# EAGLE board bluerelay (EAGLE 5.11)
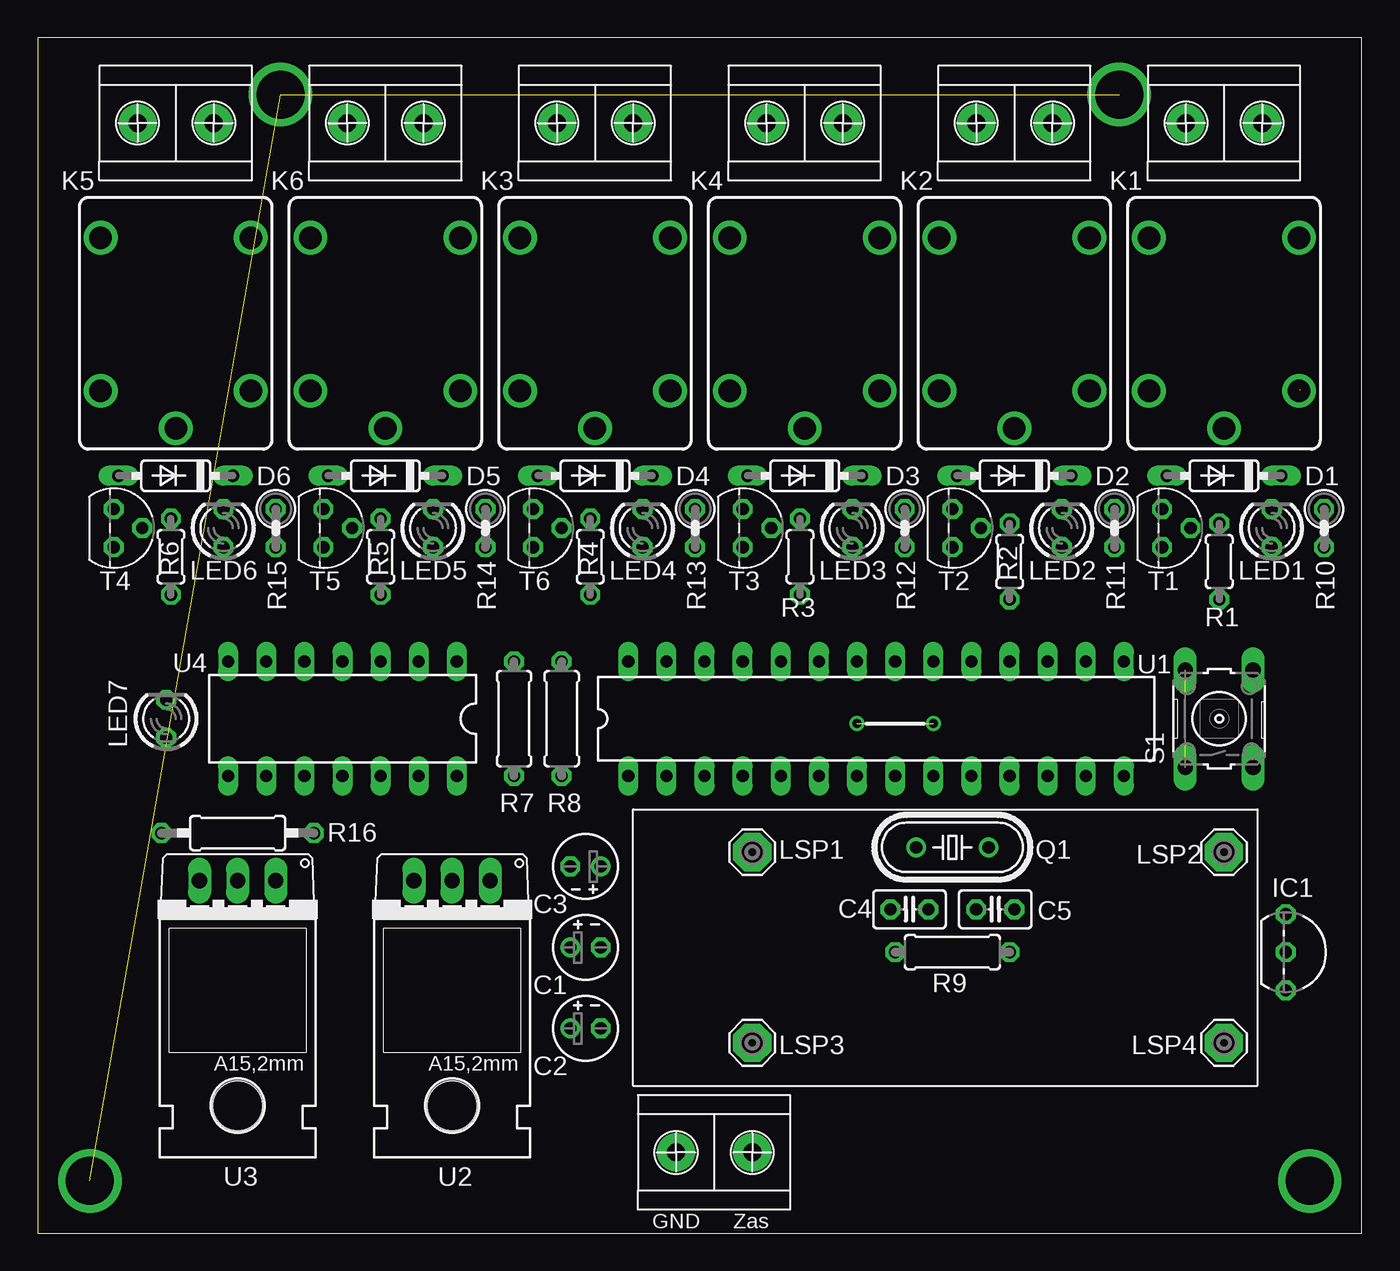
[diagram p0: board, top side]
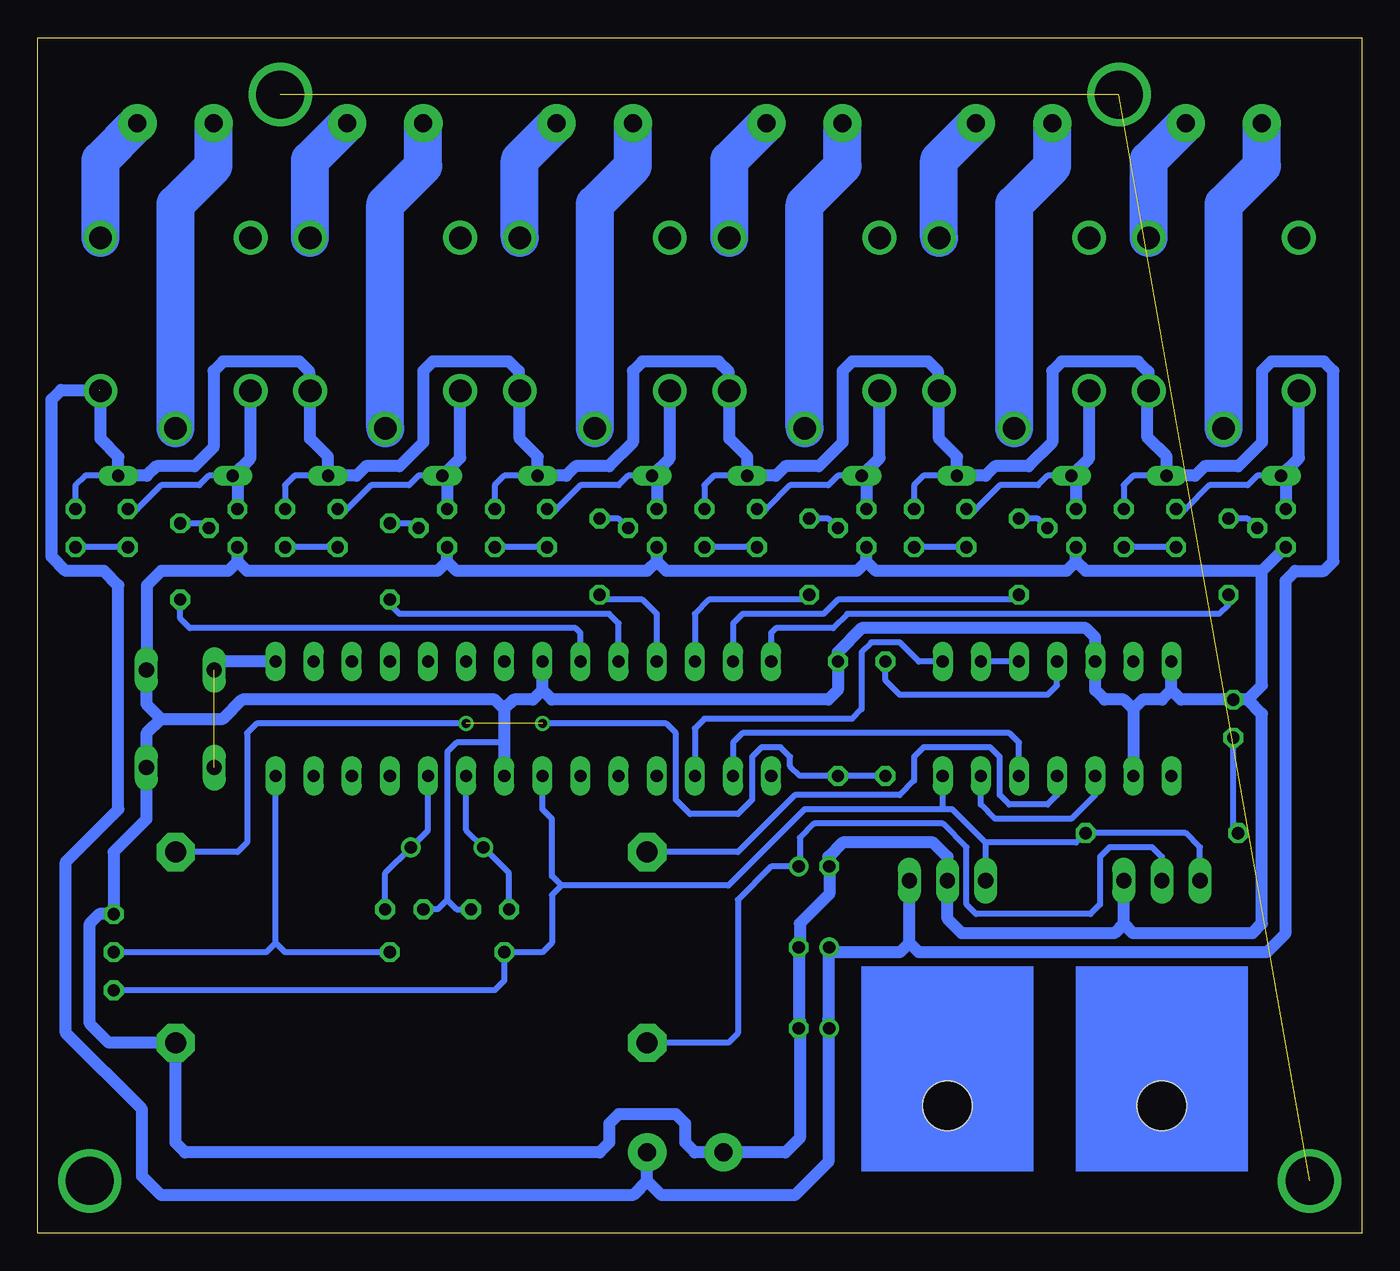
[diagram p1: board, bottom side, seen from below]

Size 88.25 x 79.68 mm. Coordinates in mm from the lower left corner, seen from the top.
Outline: 0,0 88.25,0 88.25,79.68 0,79.68 0,0
Copper layers (1*16): Top 0.035mm / dielectric 1.5mm / Bottom 0.035mm
Design rules "default": minimum track width 10mil, minimum drill 24mil, track to track 8mil, track to pad 8mil, pad to pad 8mil, via to via 8mil, smd to smd 8mil, copper to edge 40mil, drill to drill 8mil, minimum pad ring 10mil, minimum via ring 8mil, stop-mask expansion 4mil, vias tented up to drill 0mil, thermal gap 10mil

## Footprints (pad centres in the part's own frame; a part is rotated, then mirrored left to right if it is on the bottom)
E2-4 = drill 0.813 pad 1.27 round: + -1.016,0 | drill 0.813 pad 1.27 octagon: - 1.016,0
C025-025X050 = drill 0.813 octagon: 1 -1.27,0; 2 1.27,0
DO35-7 = drill 0.813 long: A 3.81,0; C -3.81,0
TO92- = drill 0.813 octagon: 1 -2.54,0; 2 0,0; 3 2.54,0
TO220V = drill 1.016 long: 1 -2.54,-2.54; 2 0,-2.54; 3 2.54,-2.54
TO220L1 = drill 1.016 long: 1 -2.54,-3.81; 2 0,-3.81; 3 2.54,-3.81 | hole 3.302: 0,11.176
CQ1 = drill 1.5 round: 1 4.5,-5; 2 4.5,5; C 7,0; NC -5.7,-5; NO -5.7,5
LED3MM = drill 0.813 octagon: A -1.27,0; K 1.27,0
SE14 = drill 1.397 pad 2.54 octagon: MP 0,0
HC49/S = drill 0.813 round: 1 -2.413,0; 2 2.413,0
0204/5 = drill 0.813 octagon: 1 -2.54,0; 2 2.54,0
0207/7 = drill 0.813 octagon: 1 -3.81,0; 2 3.81,0
0207/2V = drill 0.813 octagon: 1 -1.27,0; 2 1.27,0
0207/10 = drill 0.813 octagon: 1 -5.08,0; 2 5.08,0
B3F-10XX = drill 1.016 long: 1 -3.251,2.261; 2 3.251,2.261; 3 -3.251,-2.261; 4 3.251,-2.261
TO92 = drill 0.813 octagon: 1 1.27,0; 2 0,1.905; 3 -1.27,0
DIL28-3 = drill 0.813 long: 1 -16.51,-3.81; 2 -13.97,-3.81; 3 -11.43,-3.81; 4 -8.89,-3.81; 5 -6.35,-3.81; 6 -3.81,-3.81; 7 -1.27,-3.81; 8 1.27,-3.81; 9 3.81,-3.81; 10 6.35,-3.81; 11 8.89,-3.81; 12 11.43,-3.81; 13 13.97,-3.81; 14 16.51,-3.81; 15 16.51,3.81; 16 13.97,3.81; 17 11.43,3.81; 18 8.89,3.81; 19 6.35,3.81; 20 3.81,3.81; 21 1.27,3.81; 22 -1.27,3.81; 23 -3.81,3.81; 24 -6.35,3.81; 25 -8.89,3.81; 26 -11.43,3.81; 27 -13.97,3.81; 28 -16.51,3.81
DIL14 = drill 0.813 long: 1 -7.62,-3.81; 2 -5.08,-3.81; 3 -2.54,-3.81; 4 0,-3.81; 5 2.54,-3.81; 6 5.08,-3.81; 7 7.62,-3.81; 8 7.62,3.81; 9 5.08,3.81; 10 2.54,3.81; 11 0,3.81; 12 -2.54,3.81; 13 -5.08,3.81; 14 -7.62,3.81
ARK2 = drill 1.2 pad 2.54 round: 1 -2.54,0; 3 2.54,0 | drill 0.8 pad 2.54 round: 2 2.54,0

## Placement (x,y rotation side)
C1  [E2-4]  36.51,19.05 0 top
C2  [E2-4]  36.51,13.65 0 top
C3  [E2-4]  36.51,24.45 180 top
C4  [C025-025X050]  58.1,21.59 180 top
C5  [C025-025X050]  63.82,21.59 0 top
D1  1N4148DO35-7  [DO35-7]  79.06,50.48 180 top
D2  1N4148DO35-7  [DO35-7]  65.09,50.48 180 top
D3  1N4148DO35-7  [DO35-7]  51.12,50.48 180 top
D4  1N4148DO35-7  [DO35-7]  37.15,50.48 180 top
D5  1N4148DO35-7  [DO35-7]  23.18,50.48 180 top
D6  1N4148DO35-7  [DO35-7]  9.21,50.48 180 top
IC1  DS18S20  [TO92-]  83.19,18.73 270 top
IC5  7805TV  [TO220V]  13.33,20.95 180 top
IC6  LD117AV18  [TO220L1]  27.62,19.68 180 top
K1  CQ1-12V  [CQ1]  79.06,60.64 270 top
K2  CQ1-12V  [CQ1]  65.09,60.64 270 top
K3  CQ1-12V  [CQ1]  37.15,60.64 270 top
K4  CQ1-12V  [CQ1]  51.12,60.64 270 top
K5  CQ1-12V  [CQ1]  9.21,60.64 270 top
K6  CQ1-12V  [CQ1]  23.18,60.64 270 top
LED1  [LED3MM]  82.23,46.99 90 top
LED2  [LED3MM]  68.26,46.99 90 top
LED3  [LED3MM]  54.29,46.99 90 top
LED4  [LED3MM]  40.32,46.99 90 top
LED5  [LED3MM]  26.35,46.99 90 top
LED6  [LED3MM]  12.38,46.99 90 top
LED7  [LED3MM]  8.57,34.29 90 top
LSP1  SE14  [SE14]  47.62,25.4 0 top
LSP2  SE14  [SE14]  79.06,25.4 0 top
LSP3  SE14  [SE14]  47.62,12.7 0 top
LSP4  SE14  [SE14]  79.06,12.7 0 top
Q1  [HC49/S]  60.96,25.72 180 top
R1  [0204/5]  78.74,44.77 90 top
R2  [0204/5]  64.77,44.77 90 top
R3  [0204/5]  50.8,45.09 90 top
R4  [0204/5]  36.83,45.09 90 top
R5  [0204/5]  22.86,45.09 90 top
R6  [0204/5]  8.89,45.09 90 top
R7  3k3  [0207/7]  31.75,34.29 90 top
R8  6k8  [0207/7]  34.93,34.29 90 top
R9  3k3  [0207/7]  60.96,18.73 180 top
R10  [0207/2V]  85.72,46.99 270 top
R11  [0207/2V]  71.75,46.99 270 top
R12  [0207/2V]  57.79,46.99 270 top
R13  [0207/2V]  43.82,46.99 270 top
R14  [0207/2V]  29.84,46.99 270 top
R15  [0207/2V]  15.88,46.99 270 top
R16  [0207/10]  13.33,26.67 180 top
S1  [B3F-10XX]  78.74,34.29 90 top
T1  BC547  [TO92]  74.93,46.99 270 top
T2  BC547  [TO92]  60.96,46.99 270 top
T3  BC547  [TO92]  46.99,46.99 270 top
T4  BC547  [TO92]  5.08,46.99 270 top
T5  BC547  [TO92]  19.05,46.99 270 top
T6  BC547  [TO92]  33.02,46.99 270 top
U1  MEGA8-P  [DIL28-3]  55.88,34.29 0 top
U2  7805TV  [TO220V]  27.62,20.95 180 top
U3  LD117AV18  [TO220L1]  13.33,19.68 180 top
U4  74HCT14N  [DIL14]  20.32,34.29 180 top
U$1  ARK2  [ARK2]  79.06,73.98 180 top
U$2  ARK2  [ARK2]  65.09,73.98 180 top
U$3  ARK2  [ARK2]  37.15,73.98 180 top
U$4  ARK2  [ARK2]  51.12,73.98 180 top
U$5  ARK2  [ARK2]  9.21,73.98 180 top
U$6  ARK2  [ARK2]  23.18,73.98 180 top
U$7  ARK2  [ARK2]  45.09,5.4 180 top

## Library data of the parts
C1-C5 R1-R16 = rcl
D1-D6 = diode
IC1 = 1wire
IC5 U2 = linear
IC6 U3 = v-reg
K1-K6 = relay
LED1-LED7 = led
LSP1-LSP4 = solpad
Q1 = crystal
S1 = switch-omron
T1-T6 = transistor
U1 = atmel
U4 = 74xx-eu
U$1-U$7 = ark2

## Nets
AVCC: U1.20
GND: C1.- C2.- C3.- C4.1 C5.1 IC1.1 LED7.K LSP4.MP R8.2 S1.3 S1.4 T1.1 T2.1 T3.1 T4.1 T5.1 T6.1 U1.8 U1.22 U2.2 U3.1 U4.5 U4.7 U4.9 U$7.2
N$1: C4.2 Q1.2 U1.9
N$2: C5.2 Q1.1 U1.10
N$3: K1.NO U$1.1
N$4: R1.2 T1.2
N$5: R1.1 U1.23
N$6: R2.1 U1.24
N$7: R3.1 U1.25
N$8: R4.1 U1.26
N$9: R5.1 U1.27
N$10: R6.1 U1.28
N$11: R3.2 T3.2
N$12: R2.2 T2.2
N$13: R6.2 T4.2
N$14: R5.2 T5.2
N$15: R4.2 T6.2
N$16: D1.A K1.1 LED1.K T1.3
N$17: D2.A K2.1 LED2.K T2.3
N$18: D3.A K4.1 LED3.K T3.3
N$19: D4.A K3.1 LED4.K T6.3
N$20: D5.A K6.1 LED5.K T5.3
N$21: D6.A K5.1 LED6.K T4.3
N$22: K1.C U$1.2
N$23: K2.NO U$2.1
N$24: K2.C U$2.2
N$25: K3.NO U$3.1
N$26: K3.C U$3.2
N$27: K4.NO U$4.1
N$28: K4.C U$4.2
N$29: K5.NO U$5.1
N$30: K5.C U$5.2
N$31: K6.NO U$6.1
N$32: K6.C U$6.2
N$34: U4.10 U4.13
N$35: U4.2 U4.3
N$36: U1.2 U4.12
N$37: U1.3 U4.1
N$38: R7.2 U4.4
N$39: LSP2.MP R7.1 R8.1
N$41: LSP1.MP U4.11
N$42: C3.+ LSP3.MP U3.2
N$47: C1.+ C2.+ D1.C D2.C D3.C D4.C D5.C D6.C K1.2 K2.2 K3.2 K4.2 K5.2 K6.2 R10.1 R11.1 R12.1 R13.1 R14.1 R15.1 U2.1 U$7.1
N$50: IC1.2 R9.1 U1.14
N$51: LED1.A R10.2
N$52: S1.1 S1.2 U1.15
N$53: LED2.A R11.2
N$54: LED3.A R12.2
N$55: LED4.A R13.2
N$56: LED5.A R14.2
N$57: LED6.A R15.2
N$58: LED7.A R16.2
VCC: IC1.3 R9.2 R16.1 U1.7 U2.3 U3.3 U4.14

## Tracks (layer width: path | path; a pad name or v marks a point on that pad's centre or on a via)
GND
  Bottom 0.406: U4.5 17.78,38.42 | 60.96,22.22 61.6,21.59 C5.1 | 60.96,22.22 60.33,21.59 C4.1 | 60.96,22.22 60.96,32.07 60.33,32.7 57.15,32.7
  Bottom 0.813: 15.88,20.64 16.51,20 26.67,20 27.62,20.95 U2.2 27.62,25.08 28.57,26.04 34.61,26.04 35.56,25.08 C3.- 35.5,22.61 37.47,20.64 37.47,19.11 C1.- C2.- 37.47,14.22 37.47,6.35 38.42,5.4 U$7.2 44.45,5.4 45.09,6.03 45.09,7.3 45.72,7.94 49.53,7.94 50.17,7.3 50.17,6.03 50.8,5.4 78.42,5.4 79.06,6.03 LSP4.MP 83.5,12.7 84.77,13.97 84.77,20.64 84.14,21.27 IC1.1 83.19,25.4 81,27.58 S1.3 81,33.3 80.01,34.29 | 15.88,20.64 15.24,20 7.3,20 6.67,20.64 6.67,34.61 7.62,35.56 | 7.62,35.56 6.67,36.51 6.67,44.13 | 57.15,34.92 57.79,35.56 74.61,35.56 75.88,34.29 80.01,34.29 | 57.15,34.92 57.15,32.7 U1.8 | 57.15,34.92 56.52,35.56 55.25,35.56 54.61,36.2 | 54.61,36.2 U1.22 | 54.61,36.2 53.98,35.56 35.56,35.56 34.93,36.2 R8.2 34.93,38.73 33.34,40.32 18.41,40.32 17.78,39.69 17.78,38.42 | 7.62,35.56 LED7.K 12.06,35.56 12.7,36.2 | 12.7,36.2 U4.7 | 12.7,36.2 13.33,35.56 14.61,35.56 15.24,34.92 | 15.24,34.92 15.88,35.56 17.14,35.56 17.78,36.2 U4.5 | 15.24,34.92 U4.9 | 15.88,20.64 U3.1 | 80.01,34.29 81,35.28 S1.4 80.96,37.58 80.96,43.18 80.01,44.13 75.56,44.13 74.93,44.77 | 6.67,44.13 T4.1 | 74.93,44.77 T1.1 | 60.96,44.77 T2.1 | 60.96,44.77 61.6,44.13 74.3,44.13 74.93,44.77 | 46.99,44.77 T3.1 | 46.99,44.77 47.62,44.13 60.33,44.13 60.96,44.77 | 33.02,44.77 T6.1 | 33.02,44.77 33.66,44.13 46.36,44.13 46.99,44.77 | 19.05,44.77 T5.1 | 19.05,44.77 19.68,44.13 32.38,44.13 33.02,44.77 | 19.05,44.77 18.41,44.13 6.67,44.13
N$1
  Bottom 0.406: U1.9 59.69,26.86 Q1.2 56.83,24 C4.2
N$2
  Bottom 0.406: U1.10 62.23,26.86 Q1.1 65.09,24 C5.2
N$3
  Bottom 2.54: K1.NO 84.06,71.52 U$1.1
N$4
  Bottom 0.406: T1.2 77.15,47.31 R1.2
N$5
  Bottom 0.406: U1.23 52.07,40.01 52.39,40.32 78.1,40.32 78.74,40.96 R1.1
N$6
  Bottom 0.406: U1.24 49.53,40.64 50.17,41.27 64.14,41.27 64.77,41.91 R2.1
N$7
  Bottom 0.406: U1.25 46.99,41.27 47.94,42.23 50.48,42.23 R3.1
N$8
  Bottom 0.406: R4.1 37.15,42.23 43.5,42.23 44.45,41.27 U1.26
N$9
  Bottom 0.406: U1.27 41.91,40.64 41.28,41.27 35.88,41.27 34.93,42.23 23.18,42.23 R5.1
N$10
  Bottom 0.406: R6.1 8.89,41.91 9.53,41.27 34.29,41.27 35.24,40.32 39.05,40.32 39.37,40.01 U1.28
N$11
  Bottom 0.406: T3.2 49.53,47.62 R3.2
N$12
  Bottom 0.406: T2.2 63.18,47.31 R2.2
N$13
  Bottom 0.406: T4.2 7.62,47.62 R6.2
N$14
  Bottom 0.406: T5.2 21.59,47.62 R5.2
N$15
  Bottom 0.406: T6.2 35.56,47.62 R4.2
N$16
  Bottom 0.406: LED1.K 81.6,48.26 80.01,49.85 77.47,49.85 76.83,50.48 D1.A
  Bottom 0.813: K1.1 74.06,51.67 D1.A 74.93,50.16 T1.3
N$17
  Bottom 0.406: LED2.K 67.63,48.26 66.04,49.85 63.5,49.85 62.87,50.48 D2.A
  Bottom 0.813: K2.1 60.09,51.67 D2.A 60.96,50.16 T2.3
N$18
  Bottom 0.406: LED3.K 53.66,48.26 52.07,49.85 49.53,49.85 48.9,50.48 D3.A
  Bottom 0.813: K4.1 46.12,51.67 D3.A 46.99,50.16 T3.3
N$19
  Bottom 0.406: LED4.K 39.69,48.26 38.1,49.85 35.56,49.85 34.93,50.48 D4.A
  Bottom 0.813: K3.1 32.15,51.67 D4.A 33.02,50.16 T6.3
N$20
  Bottom 0.406: LED5.K 25.72,48.26 24.13,49.85 21.59,49.85 20.95,50.48 D5.A
  Bottom 0.813: K6.1 18.18,51.67 D5.A 19.05,50.16 T5.3
N$21
  Bottom 0.406: LED6.K 11.75,48.26 10.16,49.85 7.62,49.85 6.98,50.48 D6.A
  Bottom 0.813: K5.1 4.21,51.67 D6.A 5.08,50.16 T4.3
N$22
  Bottom 2.54: K1.C 79.06,68.58 76.52,71.12 U$1.2
N$23
  Bottom 2.54: K2.NO 70.09,71.52 U$2.1
N$24
  Bottom 2.54: K2.C 65.09,68.58 62.55,71.12 U$2.2
N$25
  Bottom 2.54: K3.NO 42.15,71.52 U$3.1
N$26
  Bottom 2.54: K3.C 37.15,68.58 34.61,71.12 U$3.2
N$27
  Bottom 2.54: K4.NO 56.12,71.52 U$4.1
N$28
  Bottom 2.54: K4.C 51.12,68.58 48.58,71.12 U$4.2
N$29
  Bottom 2.54: K5.NO 14.21,71.52 U$5.1
N$30
  Bottom 2.54: K5.C 9.21,68.58 6.67,71.12 U$5.2
N$31
  Bottom 2.54: K6.NO 28.18,71.52 U$6.1
N$32
  Bottom 2.54: K6.C 23.18,68.58 20.64,71.12 U$6.2
N$34
  Bottom 0.406: U4.10 17.78,29.21 19.37,27.62 24.45,27.62 25.4,28.57 U4.13
N$35
  Bottom 0.406: U4.3 U4.2
N$36
  Bottom 0.406: U1.2 41.91,32.7 41.28,33.34 23.5,33.34 22.86,32.7 U4.12
N$37
  Bottom 0.406: U1.3 44.45,33.66 43.82,34.29 33.97,34.29 33.34,34.92 33.34,38.73 32.7,39.37 30.8,39.37 29.53,38.1 U4.1
N$38
  Bottom 0.406: U4.4 20.32,36.51 20.95,35.88 30.8,35.88 31.75,36.83 R7.2
N$39  (via drill 0.6)  (1 unrouted)
  Bottom 0.406: R7.1 R8.1 37.47,30.48 38.1,31.11 38.1,31.75 38.74,32.38 40.01,32.38 40.64,31.75 40.64,28.89 41.59,27.94 44.77,27.94 45.72,28.89 45.72,33.34 46.36,33.97 v54.61,33.97 | v59.69,33.97 73.66,33.97 74.3,33.34 74.3,26.04 74.93,25.4 LSP2.MP
N$41
  Bottom 0.406: U4.11 20.32,29.21 20.95,28.57 23.5,28.57 24.13,29.21 24.13,31.75 24.77,32.38 29.21,32.38 29.84,31.75 29.84,30.16 30.8,29.21 37.78,29.21 41.59,25.4 LSP1.MP
N$42
  Bottom 0.406: U3.2 13.33,25.08 13.97,25.72 16.83,25.72 17.46,25.08 17.46,21.91 18.1,21.27 25.72,21.27 26.35,21.91 26.35,25.72 27.94,27.3 36.51,27.3 37.47,26.35 37.47,24.51 C3.+ 39.37,24.45 41.59,22.22 41.59,13.34 42.23,12.7 LSP3.MP
N$47  (1 unrouted)
  Bottom 0.406: 14.21,57.39 14.92,58.1 | 28.12,56.2 K6.2 28.18,57.39 28.89,58.1 | 42.09,56.2 K3.2 42.15,57.39 42.86,58.1 | 56.06,56.2 K4.2 56.12,57.39 56.83,58.1 | 70.03,56.2 K2.2 70.09,57.39 70.8,58.1 | D6.C 15.24,50.48 15.88,49.85 R15.1 | D5.C 29.21,50.48 29.84,49.85 R14.1 | D4.C 43.18,50.48 43.82,49.85 R13.1 | D3.C 57.15,50.48 57.79,49.85 R12.1 | D2.C 71.12,50.48 71.75,49.85 R11.1 | D1.C 85.09,50.48 85.72,49.85 R10.1
  Bottom 0.813: 14.29,57.47 14.92,58.1 20,58.1 20.64,57.47 20.64,52.7 22.22,51.12 24.45,51.12 25.08,50.48 D5.C 26.99,51.75 28.18,52.94 K6.2 | 28.26,56.2 28.26,57.47 28.89,58.1 33.97,58.1 34.61,57.47 34.61,52.7 36.2,51.12 38.42,51.12 39.05,50.48 D4.C 40.96,51.75 42.15,52.94 K3.2 | 42.23,56.2 42.23,57.47 42.86,58.1 47.94,58.1 48.58,57.47 48.58,52.7 50.17,51.12 52.39,51.12 53.02,50.48 D3.C 54.93,51.75 56.12,52.94 K4.2 | 56.2,56.2 56.2,57.47 56.83,58.1 61.91,58.1 62.55,57.47 62.55,52.7 64.14,51.12 66.36,51.12 66.99,50.48 D2.C 68.9,51.75 70.09,52.94 K2.2 | 70.17,56.2 70.17,57.47 70.8,58.1 75.88,58.1 76.52,57.47 76.52,52.39 77.79,51.12 80.33,51.12 80.96,50.48 D1.C 82.87,51.75 84.06,52.94 K1.2 84.11,56.2 | 47.62,3.49 48.58,2.54 80.01,2.54 81.28,3.81 81.28,8.25 86.36,13.34 86.36,24.77 82.87,28.26 82.87,43.18 83.82,44.13 86.36,44.13 87.31,45.09 87.31,55.56 86.68,56.2 84.14,56.2 | 47.62,3.49 U$7.1 | 47.62,3.49 46.67,2.54 37.78,2.54 35.56,4.76 35.56,14.29 | 30.16,19.37 29.53,18.73 6.35,18.73 5.08,20 5.08,43.5 4.45,44.13 2.54,44.13 1.91,44.77 1.91,57.47 2.54,58.1 6.03,58.1 6.67,57.47 6.67,52.7 8.26,51.12 10.48,51.12 11.11,50.48 D6.C 13.02,51.75 14.29,53.02 14.29,56.2 | 30.16,19.37 30.8,18.73 35.24,18.73 | 30.16,19.37 U2.1 | 35.56,14.29 C2.+ | C1.+ 35.5,18.99 35.24,18.73 | 35.56,14.29 35.56,18.73 35.24,18.73 | K5.2 14.21,57.39
N$48  (via drill 3.2)  (2 unrouted)
  other vias: 3.49,3.49 16.19,75.88 72.07,75.88
N$49  (via drill 3.2)
  other vias: 84.77,3.49
N$50
  Bottom 0.406: R9.1 71.75,18.73 72.39,19.37 | 72.39,19.37 U1.14 | 72.39,19.37 73.02,18.73 IC1.2
N$51
  Bottom 0.406: LED1.A R10.2
N$52  (1 unrouted)
  Bottom 0.813: U1.15 75.92,38.1 S1.2
N$53
  Bottom 0.406: LED2.A R11.2
N$54
  Bottom 0.406: LED3.A R12.2
N$55
  Bottom 0.406: LED4.A R13.2
N$56
  Bottom 0.406: LED5.A R14.2
N$57
  Bottom 0.406: LED6.A R15.2
N$58
  Bottom 0.406: R16.2 8.57,26.99 LED7.A
VCC
  Bottom 0.406: U3.3 10.79,25.72 11.75,26.67 R16.1 19.05,26.04 25.08,26.04 | 27.94,28.26 U4.14 | 25.08,26.04 27.3,28.26 27.94,28.26 | 25.08,26.04 U2.3 | U1.7 54.61,28.26 53.98,27.62 53.98,23.81 53.34,23.18 | 27.94,28.26 37.15,28.26 42.23,23.18 53.34,23.18 | 53.34,23.18 53.98,22.54 53.98,19.37 54.61,18.73 R9.2 57.15,16.83 57.79,16.19 IC1.3
(copper drawn outside any net)
  shapes: Bottom area x2

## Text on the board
tPlace: GND | Zas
